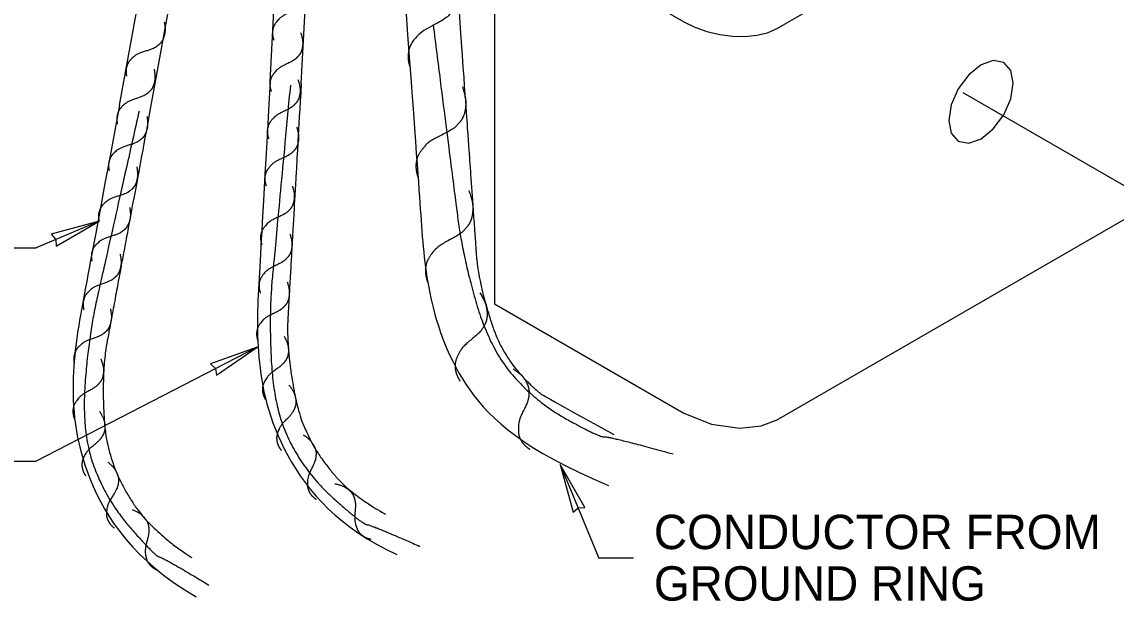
# Model space of a CAD drawing. Extents: x 99862 to 103680, y 99470 to 105076.
# Drawn here: x 101968 to 102477, y 104477 to 104746 of the extents above; entities that cross this region are included whole.
import ezdxf

# ---------------------------------------------------------------- set-up
doc = ezdxf.new("R2010")
doc.units = 0
for name, color, linetype in [('Level 1', 7, 'Continuous'), ('Level 11', 7, 'Continuous'), ('Level 15', 7, 'Continuous'), ('Level 20', 7, 'Continuous'), ('Level 5', 7, 'Continuous')]:
    doc.layers.add(name, color=color, linetype=linetype)

msp = doc.modelspace()

# ---------------------------------------------------------------- linework, layer by layer
at = {"layer": 'Level 1'}
for points in [[(102318.73, 104743.23), (102318.78, 104743.25), (102318.78, 104743.25), (102511.14, 104854.31)], [(102293.68, 104766.74), (102222.7, 104807.72), (102222.7, 104807.72), (102219.26, 104809.04), (102215.21, 104809.51), (102211.15, 104809.04), (102207.72, 104807.72), (102207.72, 104807.72), (102187.58, 104797.38), (102187.58, 104797.38), (102275.76, 104746.46), (102275.76, 104746.46), (102280.86, 104743.93), (102286.48, 104741.92), (102292.41, 104740.49), (102298.42, 104739.71), (102304.28, 104739.61), (102309.76, 104740.18), (102314.66, 104741.41), (102318.73, 104743.23)], [(102187.58, 104797.38), (102187.58, 104615.09), (102275.76, 104564.17), (102288.59, 104559.05), (102301.78, 104557.28), (102311.71, 104558.29), (102318.73, 104560.93), (102318.78, 104560.96), (102486.56, 104657.83)], [(102424.61, 104727.52), (102419.76, 104728.46), (102414.03, 104726.47), (102408.31, 104721.85), (102403.46, 104715.3), (102400.21, 104707.83), (102399.08, 104700.56), (102400.21, 104694.61), (102403.46, 104690.88), (102403.46, 104690.88)], [(102403.46, 104690.88), (102408.31, 104689.94), (102414.03, 104691.93), (102419.76, 104696.55), (102424.61, 104703.09), (102427.85, 104710.57), (102428.99, 104717.83), (102427.85, 104723.79), (102424.61, 104727.52)]]:
    msp.add_lwpolyline(points, dxfattribs=at)
at = {"layer": 'Level 11'}
for p, q in [((102013.06, 104707.59), (102028.23, 104791.25)), ((102043.56, 104794.84), (102027.26, 104704.95)), ((102083.21, 104718.57), (102085.62, 104764.63)), ((102097.64, 104717.81), (102100.05, 104763.95))]:
    msp.add_line(p, q, dxfattribs=at)
for points, degree in [([(102098.55, 104765.46), (102099.64, 104762.23), (102099.46, 104758.33), (102098.66, 104755.96), (102097.58, 104754.45), (102095.34, 104752.24), (102088.52, 104749.12), (102085.76, 104746.03), (102084.62, 104744.04), (102084.16, 104741.46), (102084.5, 104738.94), (102084.9, 104737.87)], 2), ([(102033.93, 104746.42), (102034.53, 104743.07), (102033.77, 104739.24), (102032.63, 104737.02), (102031.33, 104735.69), (102028.8, 104733.84), (102021.58, 104731.76), (102018.4, 104729.11), (102016.98, 104727.32), (102016.14, 104724.84), (102016.1, 104722.29), (102016.34, 104721.17)], 2), ([(102097.37, 104741.54), (102098.45, 104738.31), (102098.27, 104734.41), (102097.48, 104732.04), (102096.39, 104730.53), (102094.16, 104728.32), (102087.33, 104725.2), (102084.58, 104722.11), (102083.43, 104720.12), (102082.97, 104717.54), (102083.31, 104715.02), (102083.71, 104713.95)], 2), ([(102029.15, 104724.48), (102029.82, 104721.15), (102029.15, 104717.3), (102028.06, 104715.05), (102026.79, 104713.69), (102024.29, 104711.79), (102017.13, 104709.55), (102014, 104706.84), (102012.62, 104705.01), (102011.83, 104702.51), (102011.85, 104699.97), (102012.11, 104698.85)], 2), ([(102096.15, 104719.54), (102097.24, 104716.31), (102097.06, 104712.41), (102096.26, 104710.04), (102095.18, 104708.53), (102092.94, 104706.32), (102086.12, 104703.2), (102083.36, 104700.11), (102082.22, 104698.12), (102081.76, 104695.54), (102082.1, 104693.02), (102082.5, 104691.95)], 2), ([(102083.21, 104718.57), (102079.97, 104661.37), (102078.01, 104626.73), (102076.06, 104592.39), (102085.37, 104545.37), (102115.68, 104510.39), (102142.12, 104498.43)], 3), ([(102092.6, 104716.96), (102086.11, 104647.91), (102082.47, 104609.11), (102085.2, 104564.35), (102100.8, 104534.98), (102126.22, 104512.46), (102130.42, 104512.06), (102152.84, 104502.17)], 2), ([(102097.64, 104717.75), (102096.29, 104693.92), (102095.23, 104675.28), (102094.09, 104655.11), (102093.78, 104649.68), (102093.52, 104645.04), (102093.49, 104644.55), (102093.44, 104643.59), (102093.41, 104643.15), (102093.33, 104641.79), (102093.18, 104639.09), (102092.62, 104629.18), (102092.06, 104619.3), (102091.58, 104610.8), (102091.5, 104609.46), (102091.47, 104608.9), (102091.46, 104608.78), (102091.45, 104608.59), (102091.44, 104608.3), (102091.35, 104606.47), (102091.31, 104604.64), (102091.33, 104599.6), (102091.51, 104595.97), (102092.21, 104588.24), (102092.73, 104584.12), (102093.79, 104577.6), (102094.18, 104575.36), (102094.68, 104572.78), (102094.76, 104572.35), (102094.85, 104571.92), (102094.9, 104571.63), (102094.93, 104571.5), (102095.06, 104570.86), (102095.39, 104569.33), (102095.76, 104567.82), (102097.11, 104562.8), (102098.51, 104558.92), (102102, 104551.32), (102104.09, 104547.62), (102107.77, 104542.16), (102109.09, 104540.36), (102111.21, 104537.68), (102111.94, 104536.8), (102112.88, 104535.69), (102113.08, 104535.46), (102113.43, 104535.06), (102113.96, 104534.46), (102114.51, 104533.86), (102117.94, 104530.25), (102121.65, 104527.05), (102129.3, 104521.63), (102132.9, 104519.39), (102136.87, 104517.19)], 3), ([(102013.06, 104707.59), (102002.59, 104651.27), (101996.26, 104617.16), (101989.97, 104583.33), (101993.25, 104535.51), (102020.03, 104495.25), (102048.74, 104478.7)], 3), ([(102022.17, 104704.81), (102006.98, 104637.14), (101998.45, 104599.11), (101995.49, 104554.36), (102007.24, 104523.25), (102029.6, 104497.69), (102033.72, 104496.77), (102054.7, 104484.12)], 2), ([(102027.27, 104704.95), (102022.91, 104681.49), (102019.5, 104663.13), (102015.81, 104643.27), (102014.81, 104637.93), (102013.96, 104633.35), (102013.87, 104632.86), (102013.7, 104631.93), (102013.62, 104631.49), (102013.37, 104630.15), (102012.88, 104627.49), (102011.06, 104617.73), (102009.26, 104608.01), (102007.7, 104599.63), (102007.45, 104598.31), (102007.35, 104597.76), (102007.33, 104597.64), (102007.3, 104597.46), (102007.24, 104597.17), (102006.92, 104595.36), (102006.65, 104593.56), (102006.04, 104588.55), (102005.75, 104584.94), (102005.47, 104577.17), (102005.46, 104573.03), (102005.68, 104566.42), (102005.79, 104564.15), (102005.96, 104561.53), (102005.98, 104561.09), (102006.01, 104560.65), (102006.03, 104560.35), (102006.04, 104560.23), (102006.09, 104559.58), (102006.22, 104558.02), (102006.4, 104556.47), (102007.1, 104551.32), (102008, 104547.29), (102010.5, 104539.32), (102012.1, 104535.37), (102015.06, 104529.5), (102016.14, 104527.54), (102017.9, 104524.62), (102018.52, 104523.65), (102019.31, 104522.43), (102019.48, 104522.18), (102019.77, 104521.74), (102020.22, 104521.07), (102020.7, 104520.41), (102023.64, 104516.4), (102026.91, 104512.75), (102034.92, 104505.39), (102039.64, 104501.68), (102045.61, 104497.64), (102046.13, 104497.29), (102046.67, 104496.94)], 3), ([(102025.81, 104702.55), (102026.41, 104699.19), (102025.65, 104695.37), (102024.51, 104693.14), (102023.21, 104691.81), (102020.68, 104689.96), (102013.46, 104687.88), (102010.28, 104685.24), (102008.86, 104683.44), (102008.02, 104680.96), (102007.98, 104678.41), (102008.22, 104677.29)], 2), ([(102095.55, 104697.41), (102096.56, 104694.16), (102096.29, 104690.26), (102095.45, 104687.91), (102094.33, 104686.43), (102092.05, 104684.27), (102085.15, 104681.29), (102082.33, 104678.27), (102081.15, 104676.3), (102080.63, 104673.74), (102080.91, 104671.21), (102081.29, 104670.13)], 2), ([(102021.14, 104678.88), (102021.73, 104675.53), (102020.97, 104671.7), (102019.83, 104669.48), (102018.54, 104668.15), (102016, 104666.29), (102008.79, 104664.21), (102005.6, 104661.57), (102004.18, 104659.77), (102003.34, 104657.29), (102003.3, 104654.75), (102003.54, 104653.63)], 2), ([(102093.55, 104669.98), (102094.56, 104666.73), (102094.3, 104662.84), (102093.45, 104660.48), (102092.33, 104659), (102090.05, 104656.84), (102083.16, 104653.86), (102080.33, 104650.84), (102079.15, 104648.88), (102078.63, 104646.31), (102078.91, 104643.78), (102079.29, 104642.7)], 2), ([(102017.78, 104660.18), (102018.38, 104656.83), (102017.62, 104653), (102016.48, 104650.77), (102015.18, 104649.44), (102012.65, 104647.59), (102005.43, 104645.51), (102002.25, 104642.87), (102000.82, 104641.07), (101999.99, 104638.59), (101999.95, 104636.04), (102000.19, 104634.93)], 2), ([(102092.36, 104647.74), (102093.44, 104644.51), (102093.25, 104640.61), (102092.45, 104638.24), (102091.36, 104636.74), (102089.12, 104634.54), (102082.29, 104631.42), (102079.52, 104628.34), (102078.38, 104626.36), (102077.91, 104623.78), (102078.24, 104621.26), (102078.64, 104620.19)], 2), ([(102013.35, 104638.22), (102014.04, 104634.88), (102013.38, 104631.04), (102012.3, 104628.78), (102011.04, 104627.42), (102008.55, 104625.5), (102001.39, 104623.23), (101998.28, 104620.5), (101996.91, 104618.67), (101996.13, 104616.17), (101996.16, 104613.62), (101996.43, 104612.51)], 2), ([(102091.1, 104625.31), (102092.2, 104622.09), (102092.03, 104618.19), (102091.24, 104615.82), (102090.16, 104614.31), (102087.94, 104612.09), (102081.12, 104608.94), (102078.38, 104605.85), (102077.24, 104603.85), (102076.79, 104601.27), (102077.14, 104598.75), (102077.54, 104597.68)], 2), ([(102008.83, 104612.81), (102009.53, 104609.48), (102008.9, 104605.63), (102007.84, 104603.36), (102006.59, 104601.99), (102004.12, 104600.05), (101996.98, 104597.73), (101993.88, 104594.99), (101992.52, 104593.14), (101991.77, 104590.63), (101991.81, 104588.09), (101992.09, 104586.98)], 2), ([(102089.71, 104600.08), (102091.33, 104597.08), (102091.81, 104593.21), (102091.43, 104590.74), (102090.62, 104589.07), (102088.79, 104586.51), (102082.59, 104582.27), (102080.4, 104578.76), (102079.61, 104576.61), (102079.6, 104573.99), (102080.36, 104571.56), (102080.93, 104570.58)], 2), ([(102004.35, 104589.53), (102005.61, 104586.36), (102005.64, 104582.46), (102004.98, 104580.05), (102003.98, 104578.48), (102001.87, 104576.16), (101995.22, 104572.66), (101992.64, 104569.43), (101991.61, 104567.38), (101991.29, 104564.78), (101991.77, 104562.28), (101992.23, 104561.24)], 2), ([(102091.86, 104577.34), (102093.99, 104574.68), (102095.15, 104570.95), (102095.22, 104568.46), (102094.71, 104566.67), (102093.37, 104563.83), (102088.03, 104558.55), (102086.5, 104554.71), (102086.11, 104552.45), (102086.56, 104549.87), (102087.74, 104547.61), (102088.49, 104546.75)], 2), ([(102003.76, 104565.12), (102005.6, 104562.26), (102006.39, 104558.44), (102006.2, 104555.94), (102005.52, 104554.21), (102003.89, 104551.53), (101998.05, 104546.82), (101996.14, 104543.15), (101995.52, 104540.94), (101995.71, 104538.33), (101996.65, 104535.97), (101997.31, 104535.03)], 2), ([(102098.6, 104554.12), (102101.44, 104552.24), (102103.69, 104549.05), (102104.53, 104546.7), (102104.6, 104544.84), (102104.19, 104541.73), (102100.74, 104535.06), (102100.47, 104530.93), (102100.79, 104528.66), (102102.01, 104526.35), (102103.83, 104524.57), (102104.81, 104523.97)], 2), ([(102007.63, 104541.44), (102010.25, 104539.27), (102012.14, 104535.86), (102012.71, 104533.42), (102012.58, 104531.57), (102011.84, 104528.52), (102007.68, 104522.27), (102006.96, 104518.19), (102007.04, 104515.9), (102008, 104513.47), (102009.62, 104511.5), (102010.52, 104510.8)], 2), ([(102113.34, 104531.35), (102116.67, 104530.64), (102119.93, 104528.5), (102121.57, 104526.61), (102122.31, 104524.9), (102123.07, 104521.86), (102122.29, 104514.39), (102123.54, 104510.45), (102124.67, 104508.45), (102126.65, 104506.74), (102128.99, 104505.75), (102130.12, 104505.55)], 2), ([(102018.92, 104519.29), (102022.08, 104518.03), (102024.93, 104515.36), (102026.22, 104513.21), (102026.66, 104511.41), (102026.89, 104508.27), (102024.84, 104501.05), (102025.39, 104496.95), (102026.17, 104494.79), (102027.83, 104492.77), (102029.96, 104491.39), (102031.04, 104491)], 2)]:
    msp.add_open_spline(points, degree=degree, dxfattribs=at)
at = {"layer": 'Level 15'}
for p, q in [((102003.54, 104653.63), (101974.26, 104641.25)), ((101959.87, 104641.25), (101974.26, 104641.25)), ((102077.14, 104594.97), (101974.26, 104541.79)), ((101959.87, 104541.79), (101974.26, 104541.79)), ((102218.24, 104540.28), (102236.22, 104496.61)), ((102252.22, 104496.61), (102236.22, 104496.61))]:
    msp.add_line(p, q, dxfattribs=at)
for points in [[(102003.54, 104653.63), (101981.35, 104647.49), (101983.48, 104645.15), (101983.67, 104641.99)], [(102077.14, 104594.97), (102055.49, 104587.16), (102057.79, 104584.99), (102058.22, 104581.86)], [(102218.24, 104540.28), (102224.17, 104518.03), (102226.53, 104520.15), (102229.69, 104520.3)]]:
    msp.add_lwpolyline(points, close=True, dxfattribs=at)
at = {"layer": 'Level 20'}
msp.add_line((102405.58, 104713.54), (102489.67, 104665), dxfattribs=at)
at = {"layer": 'Level 5'}
for points, degree in [([(102169.84, 104768.69), (102173.53, 104716.81), (102175.17, 104693.72), (102176.24, 104678.77), (102176.55, 104674.34), (102176.62, 104673.39), (102176.65, 104672.94), (102176.75, 104671.59), (102176.94, 104668.89), (102177.64, 104658.99), (102178.34, 104649.12), (102178.95, 104640.63), (102179.04, 104639.29), (102179.08, 104638.73), (102179.09, 104638.61), (102179.1, 104638.44), (102179.12, 104638.18), (102179.25, 104636.56), (102179.42, 104634.94), (102180.02, 104630.41), (102180.61, 104627.12), (102182.17, 104620.04), (102183.16, 104616.25), (102184.94, 104610.21), (102185.59, 104608.14), (102186.38, 104605.75), (102186.51, 104605.35), (102186.64, 104604.95), (102186.73, 104604.68), (102186.77, 104604.58), (102186.95, 104604.04), (102187.4, 104602.76), (102187.88, 104601.5), (102189.59, 104597.36), (102191.22, 104594.19), (102195.05, 104588.05), (102197.26, 104585.08), (102201.09, 104580.72), (102202.45, 104579.29), (102204.62, 104577.17), (102205.37, 104576.47), (102206.24, 104575.68), (102206.38, 104575.55), (102206.53, 104575.42), (102206.62, 104575.33), (102206.66, 104575.3), (102206.87, 104575.12), (102207.36, 104574.68), (102207.88, 104574.25), (102209.07, 104573.28), (102209.97, 104572.59), (102243.11, 104554.21)], 3), ([(102170.33, 104757.31), (102170.14, 104755.81), (102169.19, 104752.91), (102167.54, 104750.6), (102164.15, 104747.2), (102153.75, 104742.35), (102149.57, 104737.6), (102147.84, 104734.55), (102147.17, 104730.6), (102147.71, 104726.75), (102148.33, 104725.12)], 3), ([(102146.27, 104752.32), (102151.1, 104686.9), (102153.43, 104653.99), (102155.87, 104619.68), (102171.09, 104574.23), (102201.14, 104547.38), (102240.61, 104530.48)], 3), ([(102159.03, 104745.18), (102167.77, 104676.38), (102172.69, 104637.72), (102185.13, 104594.63), (102206.76, 104569.38), (102236.48, 104552.95), (102240.67, 104553.48), (102270.76, 104545.22)], 2), ([(102172.65, 104716.22), (102174.34, 104711.3), (102174.1, 104705.33), (102172.91, 104701.7), (102171.26, 104699.38), (102167.87, 104695.99), (102157.47, 104691.14), (102153.29, 104686.39), (102151.56, 104683.34), (102150.89, 104679.39), (102151.43, 104675.54), (102152.05, 104673.91)], 2), ([(102175.65, 104667.85), (102177.53, 104662.99), (102177.52, 104657.03), (102176.47, 104653.35), (102174.91, 104650.98), (102171.65, 104647.45), (102161.44, 104642.21), (102157.44, 104637.31), (102155.83, 104634.19), (102155.31, 104630.22), (102155.99, 104626.4), (102156.68, 104624.79)], 2), ([(102180.81, 104620.18), (102183.29, 104616.25), (102184.3, 104611.01), (102184.01, 104607.61), (102183.05, 104605.27), (102180.79, 104601.62), (102172.74, 104595.28), (102170.08, 104590.3), (102169.2, 104587.29), (102169.42, 104583.72), (102170.68, 104580.49), (102171.55, 104579.2)], 2), ([(102196.22, 104584.92), (102199.76, 104582.6), (102202.58, 104578.64), (102203.62, 104575.71), (102203.71, 104573.4), (102203.22, 104569.52), (102198.94, 104561.22), (102198.61, 104556.09), (102199.01, 104553.26), (102200.54, 104550.39), (102202.81, 104548.18), (102204.02, 104547.44)], 2)]:
    msp.add_open_spline(points, degree=degree, dxfattribs=at)

# ---------------------------------------------------------------- texts
at = {"layer": 'Level 20'}
for s, p in [('CONDUCTOR FROM', (102261.79, 104500.88)), ('GROUND RING', (102261.79, 104476.88))]:
    msp.add_text(s, height=16, dxfattribs=at).set_placement(p)

doc.saveas('drawing.dxf')
